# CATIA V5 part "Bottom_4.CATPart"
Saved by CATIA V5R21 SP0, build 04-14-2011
Part number: Part1.5
Material "DS Yellow": density 7860 kg/m3, Young's modulus 2e+11 Pa, Poisson ratio 0.266
Bounding box of the stored display mesh (mm): x 0 to 45, y -17 to 17, z -17 to 17
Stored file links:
  C:\Users\RIAD MAHAMUD PIASH\Desktop\Project\Bottom_4.CATPart
  C:\Program Files (x86)\Dassault Systemes\B21\intel_a\startup\materials\yellow_env_512x512.jpg
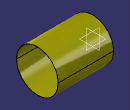
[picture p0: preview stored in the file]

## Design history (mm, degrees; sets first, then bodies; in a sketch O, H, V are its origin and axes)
Body1 (main body), material "DS Yellow"
  Sketch1 on yz-plane, origin (0, 0, 0), H (0, 1, 0), V (0, 0, 1)
    circle A1 centre (0, 0) radius 17
    circle A2 centre (0, 0) radius 16.9
    radius A1 = 17
    radius A2 = 16.9
  Pad1: profile Sketch1, direction (1, 0, 0), length 45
